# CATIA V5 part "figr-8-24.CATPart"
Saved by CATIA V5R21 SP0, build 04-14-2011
Part number: Part1
Bounding box of the stored display mesh (mm): x -50 to 50, y -62.5 to 62.5, z 0 to 10
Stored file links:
  D:\CATIA V5R21 E-RESOURCES\CATIA-V5R21\catia-v5r21-prt\c08-catia-v5r20-prt\c08-catia-v5r21-figr-8-24.CATPart
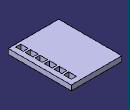
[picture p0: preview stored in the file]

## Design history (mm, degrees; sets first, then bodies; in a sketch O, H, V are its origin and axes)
Body1 (main body)
  Sketch1 on xy-plane, origin (0, 0, 0), H (1, 0, 0), V (0, 1, 0)
    line L1 (-50, 62.5) -> (50, 62.5)
    line L2 (50, 62.5) -> (50, -62.5)
    line L3 (50, -62.5) -> (-50, -62.5)
    line L4 (-50, -62.5) -> (-50, 62.5)
    axis line L5 (50, -62.5) -> (-50, 62.5)
    length L3 = 100
    length L2 = 125
    horizontal: L1 H, L3 H
    vertical: L2 V, L4 V
    midpoint: O L5
  Pad1: profile Sketch1, direction (0, 0, 1), length 10
  Sketch2 on face of Pad1, origin (0, 0, 10), H (1, 0, 0), V (0, 1, 0)
    line L1 (40, -57.5) -> (30, -57.5)
    line L2 (30, -57.5) -> (30, -42.5)
    line L3 (30, -42.5) -> (40, -42.5)
    line L4 (40, -42.5) -> (40, -57.5)
    reference projected line E1 (-50, -62.5) -> (50, -62.5) from edge [face of Pad1 | face of Pad1]
    reference projected line E2 (50, -62.5) -> (50, 62.5) from edge [face of Pad1 | face of Pad1]
    length L1 = 10
    length L4 = 15
    distance L1 E1 = 5
    distance L4 E2 = 10
    horizontal: L1 H, L3 H
    vertical: L2 V, L4 V
  Pocket1: profile Sketch2, direction (0, 0, -1), through (limit type 3)
  RectPattern1: of Pocket1, direction 1 instances 6, spacing 19, along edge [face of Pad1 | face of Pad1], direction 2 instances 6, spacing 15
